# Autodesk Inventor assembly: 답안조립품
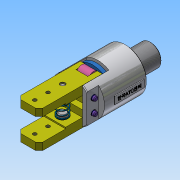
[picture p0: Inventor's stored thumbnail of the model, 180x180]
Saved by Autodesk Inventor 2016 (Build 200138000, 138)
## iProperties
Created: 2019-02
Part Number: 답안조립품
Material: 일반
Document SubType Name: Assembly
Designer: Administrator
Author: Administrator
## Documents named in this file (11)
- C:\Users\Administrator\Desktop\490207V1019\답안조립품.iam
- C:\Users\Administrator\Desktop\490207V1019\본체.ipt
- C:\Users\Administrator\Desktop\490207V1019\E-링.ipt
- C:\Users\Administrator\Desktop\490207V1019\O-링.ipt
- C:\Users\Administrator\Desktop\490207V1019\가이드핀.ipt
- C:\Users\Administrator\Desktop\490207V1019\부시.ipt
- C:\Users\Administrator\Desktop\490207V1019\스프링.ipt
- C:\Users\Administrator\Desktop\490207V1019\평행핀 6x28.ipt
- C:\Users\Administrator\Desktop\490207V1019\피스톤.ipt
- C:\Users\Administrator\Desktop\490207V1019\핀.ipt
- C:\Users\Administrator\Desktop\490207V1019\핑거.ipt
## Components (11 placed, 6 different names)
1. E-링:1
2. O-링:1
3. 가이드핀:1
4. 피스톤:1
5. 핀:1
6. 핑거:1
7. 핑거:2
8. 가이드핀:2
9. 핀:2
10. E-링:2
11. O-링:2
